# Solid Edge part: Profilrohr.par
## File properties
Username: ahadarics
Dokumentum tartalom típus: 0
Author: ahadarics
Last saved by: ahadarics
Revision: 83
Sűrűség: 0,000 kg/m^3
Pontosság: 0,990
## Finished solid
Body 1: solid body, 6 faces, 6 edges, 0 vertices.
  Faces by surface: cone 2, cylinder 2, plane 2
  Edges by curve: circle 6
Bounding box of the edges (mm): 21.270 x 21.270 x 232.000, from (-10.635, -10.635, -21) to (10.635, 10.635, 211).
Cylindrical faces by radius (mm): R10 x1, R10.635 x1
Conical faces (half-angle, radius in mm at the cone's reference point): 15 deg R10.067 x2
Planar faces by outward normal: +z 1, -z 1
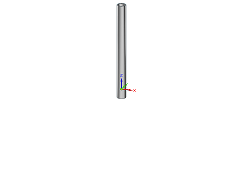
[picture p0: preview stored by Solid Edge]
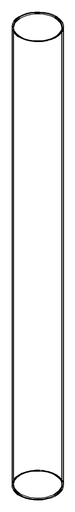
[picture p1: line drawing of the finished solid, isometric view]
